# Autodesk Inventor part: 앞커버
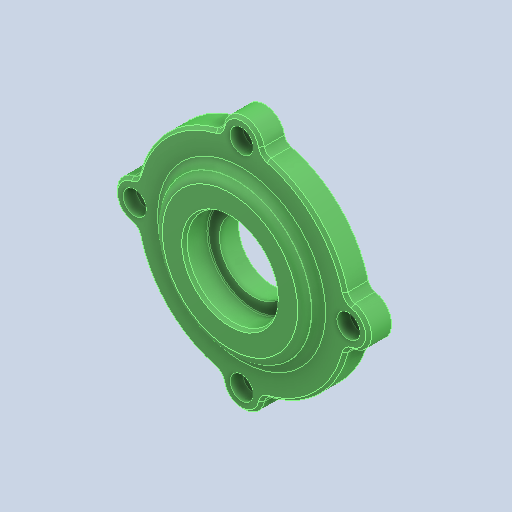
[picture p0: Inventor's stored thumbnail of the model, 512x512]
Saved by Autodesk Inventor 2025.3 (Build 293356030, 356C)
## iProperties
Created: 2025-08
Part Number: 앞커버
Material: 알루미늄 6061
Document SubType Name: Modeling
Designer: user
Density: 2.71 g/cm^3
Appearance: 기본값
Company: 한국ATC센터
Author: jhkim
Sending System: Autodesk Inventor 2026
Preprocessor: ST-DEVELOPER v20.1
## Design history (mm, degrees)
sketch "스케치1"
  geometry: 1 further point
  constraints: 1 other
feature "솔리드1"
node "솔리드2"
